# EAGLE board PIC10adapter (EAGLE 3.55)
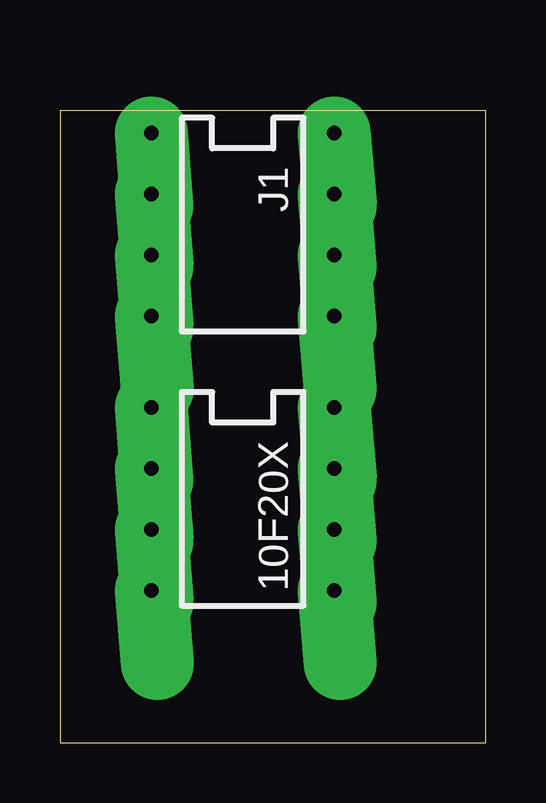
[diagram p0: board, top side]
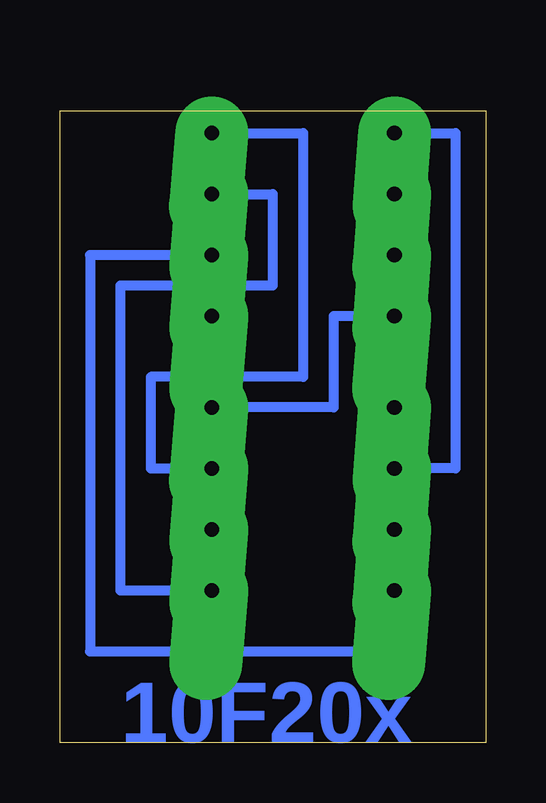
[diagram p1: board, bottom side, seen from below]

Size 17.76 x 26.34 mm. Coordinates in mm from the lower left corner, seen from the top.
Outline: 0,0 17.76,0 17.76,26.34 0,26.34 0,0
Copper layers used: Bottom

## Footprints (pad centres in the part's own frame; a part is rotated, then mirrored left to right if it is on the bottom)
L-8B = drill 0.61 pad 3.048 offset:  0,0;  2.54,0;  5.08,0;  7.62,0;  7.62,7.62;  5.08,7.62;  2.54,7.62;  0,7.62

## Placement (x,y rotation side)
10F20X  DIP8  [L-8B]  3.81,13.97 270 top
J1  DIP8  [L-8B]  3.81,25.4 270 top

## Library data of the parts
10F20X J1 = 8031bord

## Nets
ICSPCLK: 10F20X. J1.
ICSPDAT: 10F20X. J1.
VDD: 10F20X. J1.
VPP: 10F20X. J1.
VSS: 10F20X. J1.

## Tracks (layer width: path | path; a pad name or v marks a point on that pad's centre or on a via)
ICSPCLK
  Bottom 0.406: 11.43,20.32 16.51,20.32 16.51,3.81 3.81,3.81 3.81,6.35
ICSPDAT
  Bottom 0.406: 11.43,22.86 8.89,22.86 8.89,19.05 15.24,19.05 15.24,6.35 11.43,6.35
VDD
  Bottom 0.406: 3.81,25.4 1.27,25.4 1.27,11.43 3.81,11.43
VPP
  Bottom 0.406: 3.81,17.78 6.35,17.78 6.35,13.97 10F20X.
VSS
  Bottom 0.406: J1. 7.62,25.4 7.62,15.24 13.97,15.24 13.97,11.43 11.43,11.43

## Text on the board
Bottom: 10F20x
